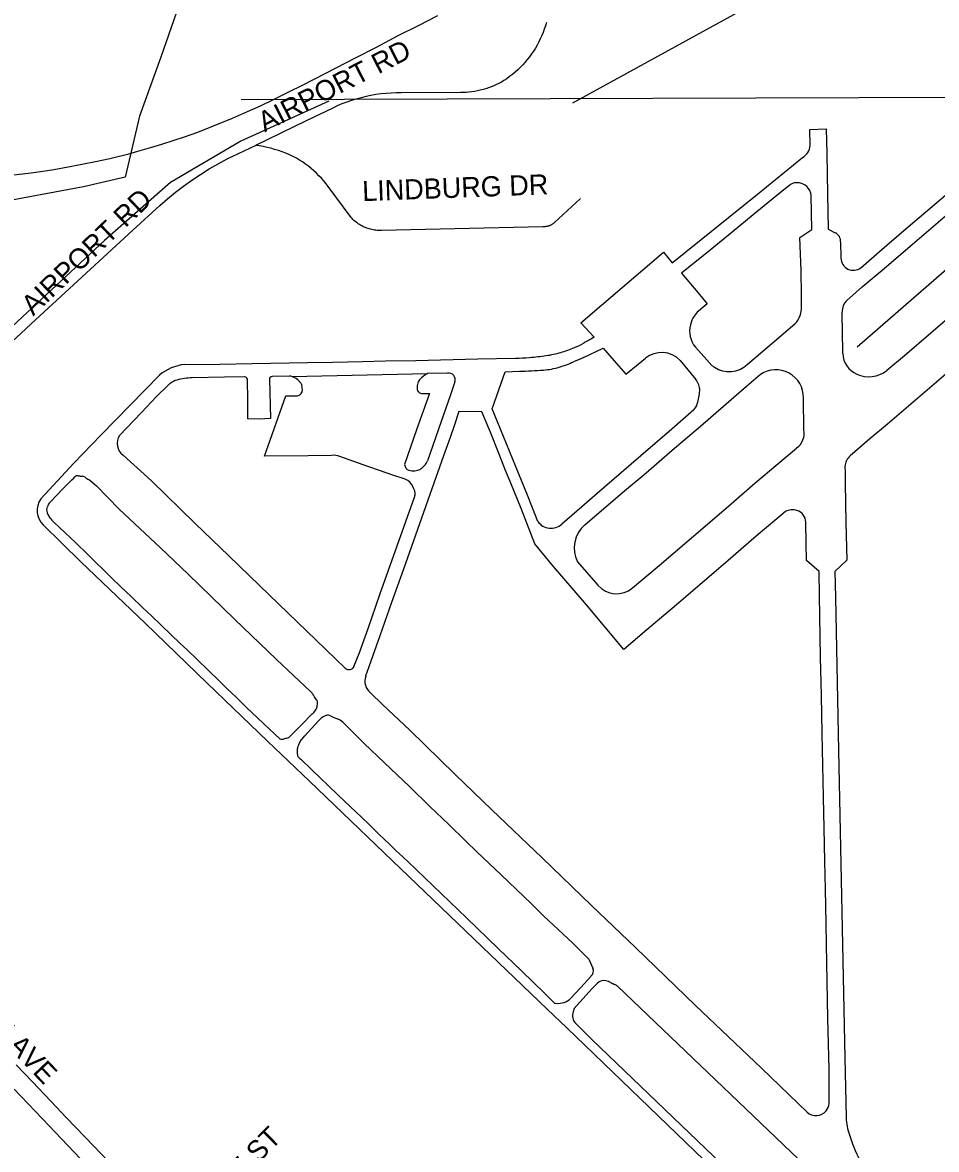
# Model space of a CAD drawing. Extents: x 1670563 to 1761545, y 515755 to 578944.
# Drawn here: x 1710407 to 1713800, y 545541 to 549724 of the extents above; entities that cross this region are included whole.
import ezdxf

# ---------------------------------------------------------------- set-up
doc = ezdxf.new("R2010")
doc.units = 0
for name, color, linetype in [('5_sectionlines', 7, 'Continuous'), ('AIRPORT', 7, 'Continuous'), ('RR Tracks', 7, 'Continuous'), ('SHP_LINE', 7, 'Continuous'), ('STREETCL', 7, 'Continuous'), ('STRNAMES', 7, 'Continuous')]:
    doc.layers.add(name, color=color, linetype=linetype)

# ---------------------------------------------------------------- blocks, each defined once
blk = doc.blocks.new('RR TRACKS02')
at = {"layer": 'RR Tracks'}
for p, q in [((1711947.7, 549748.9), (1711876.3, 549712.5)), ((1711876.3, 549712.5), (1711800.9, 549674.7)), ((1711800.9, 549674.7), (1711720, 549632.1)), ((1711720, 549632.1), (1711641.8, 549592)), ((1711641.8, 549592), (1711570.6, 549555.3)), ((1711570.6, 549555.3), (1711491.1, 549514)), ((1711440.4, 549488.5), (1711400, 549468.4)), ((1711491.1, 549514), (1711440.4, 549488.5)), ((1711337.9, 549437.6), (1711288.8, 549414.2)), ((1711400, 549468.4), (1711337.9, 549437.6)), ((1711288.8, 549414.2), (1711241.5, 549392.8)), ((1711185.1, 549367.8), (1711115.1, 549339.7)), ((1711241.5, 549392.8), (1711185.1, 549367.8)), ((1711056.3, 549316.3), (1711006.8, 549299.3)), ((1711115.1, 549339.7), (1711056.3, 549316.3)), ((1710922.7, 549271.8), (1710886.1, 549260.1)), ((1710969.3, 549286.4), (1710922.7, 549271.8)), ((1711006.8, 549299.3), (1710969.3, 549286.4)), ((1710797.1, 549235.2), (1710731.2, 549219.1)), ((1710833.6, 549245.2), (1710797.1, 549235.2)), ((1710886.1, 549260.1), (1710833.6, 549245.2)), ((1710576.2, 549187.2), (1710523, 549178.3)), ((1710678, 549207.4), (1710576.2, 549187.2)), ((1710731.2, 549219.1), (1710678, 549207.4)), ((1710407.4, 549162.2), (1710363.3, 549157.2)), ((1710438.8, 549165.7), (1710407.4, 549162.2)), ((1710499.3, 549173.9), (1710438.8, 549165.7)), ((1710523, 549178.3), (1710499.3, 549173.9)), ((1710384.2, 545855.4), (1710443.9, 545792.5)), ((1710443.9, 545792.5), (1710512.1, 545721)), ((1710512.1, 545721), (1710570.5, 545659.5)), ((1710570.5, 545659.5), (1710672.4, 545554)), ((1710672.4, 545554), (1710723.3, 545499.8))]:
    blk.add_line(p, q, dxfattribs=at)

msp = doc.modelspace()

# ---------------------------------------------------------------- linework, layer by layer
at = {"layer": '5_sectionlines'}
msp.add_line((1711218.5, 549438.3), (1714928.9, 549450.5), dxfattribs=at)
at = {"layer": 'AIRPORT'}
for points in [[(1713518.6, 548814), (1713588.3, 548874.7), (1713678.7, 548952.4), (1713817, 549070.1), (1713965, 549196), (1714098.4, 549308.4), (1714214.1, 549408.5), (1714289.7, 549474.3), (1714442.7, 549605.3), (1714538.1, 549688), (1714676.6, 549805.6), (1714813.3, 549922.6), (1714999.3, 550082), (1715171.6, 550229.9), (1715311.3, 550349.1), (1715419.2, 550442.5), (1715536.6, 550543), (1715643.7, 550634.5), (1715877.5, 550835.4), (1715970.6, 550913.6), (1716027.7, 550962.1), (1716141.7, 551060.4), (1716262, 551162.7)], [(1715379.7, 549742.6), (1715276.1, 549654.1), (1715180.7, 549572.3), (1715079.1, 549485.6), (1714992.5, 549412.2), (1714945.8, 549371.5), (1714858.7, 549296.9), (1714764, 549215.3), (1714651.7, 549119.5), (1714580.5, 549058.3), (1714498.4, 548988.4), (1714403.7, 548907.2), (1714321, 548836.5), (1714242.8, 548769.1), (1714177.9, 548713.7), (1714074.7, 548624.8), (1713983.7, 548547.3), (1713915.4, 548488.6), (1713825.5, 548411.7), (1713705, 548308.4), (1713617.6, 548234), (1713552.5, 548179.1), (1713479.7, 548116.1)], [(1713467.3, 548693), (1713524.6, 548743.2), (1713605.2, 548811.4), (1713711.3, 548901.3), (1713806.2, 548983.5), (1713915, 549076.9), (1714014, 549161.9), (1714113.8, 549247.2), (1714197.9, 549318.9), (1714378.3, 549472.6)], [(1713331.1, 549268.4), (1713329.7, 549327.9), (1713390.1, 549329.6), (1713392.7, 549238.3), (1713395.3, 549087.7), (1713397.3, 548957.7), (1713424.5, 548944.3)], [(1714575.4, 549255.1), (1714472.4, 549165.4), (1714364.8, 549072.9), (1713974.3, 548739.8), (1713680.9, 548487.7), (1713615.2, 548433.4)], [(1712529, 548556), (1712480.2, 548609.7), (1712786.6, 548872.7), (1712819.2, 548833.1), (1713135.4, 549087.8), (1713302.5, 549223.3)], [(1713255.9, 549120.9), (1713220.6, 549093), (1713120, 549010.6), (1713041.9, 548946.4), (1712960, 548880.1), (1712853.5, 548794.4), (1712913.9, 548723), (1712949, 548680.9), (1712916, 548653.7)], [(1713337.3, 548956.4), (1713334.6, 549082)], [(1713298.4, 548712.1), (1713297.9, 548803.6), (1713293.2, 548926.7), (1713337.3, 548956.4)], [(1713443.9, 548910.3), (1713445.4, 548849.5)], [(1713298.4, 548671.1), (1713298.4, 548712.1)], [(1713452.1, 548495.7), (1713450.8, 548580.9), (1713449.9, 548636.8), (1713449.6, 548649.8)], [(1713097.7, 548455.3), (1713213.4, 548554), (1713275.6, 548607.2)], [(1712489.3, 548480.7), (1712562.9, 548515.3), (1712603.6, 548468.7), (1712647.1, 548418.7), (1712692.9, 548456.6)], [(1712904.9, 548519.3), (1712947.2, 548472), (1712966.4, 548451.7)], [(1711008.9, 548455), (1711139.4, 548456.8), (1711260.2, 548458.3), (1711464.6, 548463.1), (1711558.3, 548464.2), (1711668.8, 548466.8), (1711754.3, 548468.6), (1711866.9, 548469.9), (1712097.9, 548476), (1712237.6, 548478.7)], [(1712692.9, 548456.6), (1712719.4, 548478.1)], [(1712848.7, 548470.1), (1712907.2, 548399.4)], [(1710697.8, 548192.8), (1710915.7, 548415.7)], [(1711231.8, 548409.2), (1711157.3, 548407.7), (1711037, 548405.6)], [(1711323.6, 548400.8), (1711327.2, 548254.3), (1711285.6, 548252.7), (1711243.9, 548253.8), (1711243.1, 548326.2), (1711242.8, 548396.3)], [(1711398.1, 548412.2), (1711334, 548410.7)], [(1711407.2, 548410.5), (1711911.1, 548422)], [(1712012.4, 548391), (1711994.8, 548339.1), (1711961.4, 548244), (1711910.8, 548097)], [(1711985.2, 548423), (1711911.1, 548422)], [(1712319.7, 547872.7), (1712283.9, 547964), (1712237.2, 548078.6), (1712170.9, 548241.8), (1712151.1, 548291), (1712199, 548427.6), (1712252.6, 548429.8)], [(1713146.2, 548417.7), (1713094.9, 548373.8), (1713018.9, 548308), (1712924.3, 548225.6), (1712819.3, 548136.5), (1712721.8, 548052.4), (1712634.6, 547979.3), (1712494.5, 547859.4)], [(1710946.1, 548377.5), (1710904.2, 548335.8), (1710849.4, 548277.1), (1710767.4, 548191.7)], [(1711554.4, 548117.9), (1711467.3, 548116.4), (1711304.9, 548114.6), (1711384.3, 548338.9), (1711427.9, 548338.9)], [(1711891.4, 548347.5), (1711917.7, 548347.5), (1711871, 548216.9), (1711825.7, 548083.4)], [(1713307.7, 548212.7), (1713306, 548330.5)], [(1712217.4, 548020.5), (1712200.5, 548061.5), (1712176.5, 548122.6), (1712142.6, 548206.9), (1712112.7, 548279.7), (1712026.7, 548280.4), (1712009.1, 548227.9), (1711994.1, 548183.7), (1711970, 548115.7)], [(1712899.3, 548286.4), (1712817.1, 548215), (1712702.3, 548115.8), (1712567.5, 548000.1), (1712409.4, 547862.2)], [(1710597.5, 548088.6), (1710697.8, 548192.8)], [(1712672.1, 547626.2), (1712770.8, 547708.7), (1712882.3, 547804.8), (1713028.3, 547929.9), (1713126.1, 548014.4), (1713210.5, 548086.6), (1713280.9, 548145.2)], [(1710780.3, 548118.6), (1710885.5, 548022.8), (1711048.2, 547865.3), (1711173.5, 547744.5), (1711286.3, 547634.6), (1711393.3, 547532.6), (1711497.8, 547432.5), (1711605.2, 547328.3)], [(1711827.7, 548029.6), (1711782.3, 548044.4), (1711672.1, 548083.3), (1711585.4, 548113.8)], [(1711970, 548115.7), (1711926.6, 547993.5), (1711888.6, 547885.1), (1711821.7, 547695.9), (1711776.7, 547571.6), (1711733.2, 547448.3), (1711693.1, 547333), (1711680.9, 547298.8)], [(1710475.1, 547956), (1710597.5, 548088.6)], [(1713460, 548076.5), (1713460.7, 548056.3), (1713461.4, 548014.2), (1713464, 547868.5), (1713467.3, 547728.8), (1713423, 547686.9), (1713425.5, 547590.4), (1713435.9, 547022.3), (1713459.6, 545881), (1713464.6, 545659.8)], [(1710509.7, 547944.4), (1710535.4, 547971.8), (1710555.4, 547992), (1710590.3, 548026.7), (1710596.3, 548032.5), (1710602, 548038.1)], [(1710656.9, 548026.2), (1710681.7, 548004.9), (1710766.2, 547918.6), (1710918.9, 547775), (1711021.8, 547676.3), (1711194.2, 547509.8), (1711350.6, 547359.6), (1711476.6, 547241.5)], [(1713239, 547909.6), (1713207.8, 547882.8), (1713131.2, 547817.5), (1713026.4, 547727.4), (1712992.2, 547697.8), (1712921, 547637.2), (1712834.5, 547563.2), (1712725.3, 547470.1), (1712639.4, 547397.6), (1712501.2, 547563.4), (1712371, 547714.3), (1712308.9, 547789.8), (1712258.4, 547920.6), (1712217.4, 548020.5)], [(1711637.7, 547333.8), (1711656.3, 547382.7), (1711690.1, 547475.5), (1711733.9, 547601.5), (1711862.9, 547963.3)], [(1710623.2, 547722.9), (1710484, 547859.8)], [(1711361.9, 547065.7), (1711342.3, 547084), (1711302.2, 547122.5), (1711237.8, 547183.3), (1711200.2, 547220), (1711166, 547252.3), (1711136.8, 547281.1), (1711097.7, 547318.8), (1711053.8, 547361.6), (1711018.2, 547395.5), (1710991.2, 547421.1), (1710959.1, 547452), (1710922.2, 547488.1), (1710886.2, 547522.2), (1710854.2, 547552.5), (1710810.6, 547594.5), (1710771.5, 547631.6), (1710737.4, 547663.5), (1710647.8, 547750.8), (1710604.8, 547793.5), (1710544.9, 547850.6), (1710523.6, 547870.3)], [(1713402.1, 545722.3), (1713401.5, 545837.7), (1713396.6, 546029.1), (1713391.8, 546302.4), (1713390.4, 546380.4), (1713387.7, 546507.5), (1713385.5, 546612.1), (1713383.1, 546734.7), (1713380.7, 546848.8), (1713375.4, 547087.1), (1713372.6, 547226.2), (1713369.6, 547368.9), (1713365.3, 547597.5), (1713363.9, 547686.9), (1713317.6, 547728.2), (1713316.8, 547792.3), (1713315, 547870)], [(1710863.4, 547493.5), (1710623.2, 547722.9)], [(1712467.4, 547723.1), (1712542.6, 547635.9)], [(1711092.8, 547272.7), (1710863.4, 547493.5)], [(1711316.8, 547057.4), (1711092.8, 547272.7)], [(1711699, 547236.3), (1711743.1, 547192.8), (1711844.8, 547098.4), (1712013.5, 546932.7), (1712149.8, 546802.4), (1712336.4, 546624.3), (1712519.9, 546447.1), (1712682.6, 546290.9), (1712905.8, 546076.2), (1713149.9, 545843.2), (1713319.7, 545680.3)], [(1711482.7, 547158.2), (1711443.7, 547118.5), (1711398.1, 547072.6), (1711394.3, 547069.1)], [(1711442.3, 547062.4), (1711455.6, 547076.9), (1711479.8, 547103.9), (1711506.4, 547132.5), (1711514.8, 547140.9)], [(1711550.1, 547151.4), (1711560.4, 547146.7), (1711576.5, 547139.7)], [(1711595.7, 547127.6), (1711617, 547106.9), (1711675.7, 547048.9), (1711750.7, 546977.2), (1711843.6, 546888.3), (1711919.8, 546814.3), (1711989.9, 546747.7), (1712053, 546685.8), (1712093.4, 546646.3), (1712183.9, 546560.7), (1712296.6, 546453.2), (1712343, 546408), (1712450.5, 546307.2), (1712510, 546247.7)], [(1711472.8, 546909), (1711316.8, 547057.4)], [(1712379.3, 546087.3), (1712366.8, 546099.7), (1712344.6, 546121.7), (1712260.9, 546203.1), (1712172.8, 546287.6), (1712055.8, 546401), (1711839.1, 546609), (1711820.4, 546625.9), (1711807.1, 546639), (1711793.4, 546651.8), (1711768.9, 546674.8), (1711729.7, 546712.4), (1711691.3, 546750.3), (1711666.2, 546773.5), (1711624, 546814.6), (1711579.5, 546857), (1711541.9, 546892.8), (1711513.3, 546920.2), (1711481.6, 546951), (1711439.9, 546989.7)], [(1711750, 546642.3), (1711472.8, 546909)], [(1712354.9, 546061.7), (1711750, 546642.3)], [(1712510, 546247.7), (1712524.4, 546214.2)], [(1712517.3, 546184.1), (1712479.6, 546142.3), (1712441.2, 546101.5)], [(1712541.3, 546158.6), (1712521.2, 546137.4), (1712455.6, 546064.8), (1712451.4, 546052.6)], [(1713484.7, 545316.9), (1712615.7, 546147.6)], [(1712427.2, 545992.9), (1712354.9, 546061.7)], [(1712461.1, 546008.5), (1712520.8, 545949.4), (1713303.5, 545198.5), (1713354, 545151.7)], [(1713175.6, 545272.9), (1712427.2, 545992.9)], [(1713401.8, 545711.7), (1713402.1, 545722.3)], [(1713477.5, 545595.5), (1713488.8, 545562)]]:
    msp.add_lwpolyline(points, dxfattribs=at)
for centre, radius, start, end in [((1713273.6, 549273.3), 57.7, 300.0178, 355.1523), ((1713277.1, 549097.8), 31.4, 111.7027, 132.5024), ((1713282, 549085.6), 44.5, 78.318, 111.7027), ((1713278.4, 549068.3), 62.1, 50.1029, 78.318), ((1713289, 549081), 45.6, 1.2206, 50.1029), ((1713409.1, 548912.9), 34.9, 355.7562, 63.7629), ((1713491.2, 548850.7), 45.8, 181.4075, 306.7105), ((1713507.8, 548651.2), 58.2, 134.0763, 181.369), ((1713073.1, 548512.9), 210.9, 138.1428, 144.8238), ((1713210.7, 548666.4), 87.8, 317.6608, 3.1192), ((1712980.4, 548580), 96.8, 166.3678, 218.802), ((1712976.6, 548580.9), 92.9, 144.8238, 166.3678), ((1712336.2, 548765), 273.8, 284.6323, 295.869), ((1712396.5, 548695.6), 186.6, 288.4827, 300.7304), ((1712920.3, 547814.5), 838.5, 117.8236, 120.7304), ((1712221.7, 549282.1), 803.5, 271.1327, 274.8213), ((1712170.9, 549884.2), 1407.8, 274.8213, 277.365), ((1712293.4, 548876.5), 392.7, 278.4932, 286.5706), ((1713029.7, 547155.5), 1431.1, 112.1874, 113.8039), ((1712779.7, 548403.8), 95.7, 43.8429, 129.0195), ((1713541.7, 548500.5), 89.8, 183.0368, 245.0352), ((1711024.3, 548288.5), 167.2, 95.2742, 130.4699), ((1712129.8, 551440), 3012.7, 272.3367, 274.0214), ((1712322.4, 548700.9), 266.9, 274.0214, 286.8144), ((1712266.6, 548885.4), 459.6, 286.8144, 293.8039), ((1712988.1, 548472.3), 29.9, 223.4228, 245.701), ((1713030.3, 548527.4), 98.8, 236.5412, 313.0437), ((1713203.9, 548333.4), 102.2, 358.38, 124.3593), ((1713548.2, 548514.4), 105.1, 245.0352, 309.5557), ((1710999.4, 548328.4), 71.5, 105.7964, 126.4557), ((1711040.9, 548181.8), 223.9, 90.9987, 105.7964), ((1711229.7, 548396.3), 13.2, 0.1848, 80.5881), ((1711334.2, 548400), 10.7, 91.2613, 175.8478), ((1711396.3, 548377.1), 35.1, 71.9811, 87.0144), ((1711386, 548347.4), 66.5, 40.9863, 71.4252), ((1711401.1, 548356.6), 49.2, 30.6522, 44.4825), ((1711904.9, 548377.1), 32, 137.844, 172.0747), ((1711964.4, 548323.2), 112.3, 118.3283, 137.844), ((1711988.9, 548398.6), 24.7, 342.008, 98.6414), ((1712860.2, 548360.6), 60.9, 357.6745, 39.5931), ((1711115.4, 548171.4), 266.8, 126.4557, 129.3978), ((1711424.9, 548360), 21.3, 278.0211, 6.501), ((1711364.5, 548361.2), 81.6, 0.8347, 14.5494), ((1711991.4, 548365.1), 119.3, 172.0747, 179.7405), ((1711890.2, 548365.5), 18.1, 179.7405, 273.9076), ((1712743, 548365.3), 178.2, 341.6137, 357.6745), ((1712847.7, 548330.5), 67.9, 319.5002, 341.6137), ((1710812.1, 548161.9), 53.7, 146.2507, 233.6743), ((1713241.7, 548199.9), 67.3, 305.6683, 11.0004), ((1711560, 548041.5), 76.6, 70.6139, 94.1537), ((1711846.7, 548127.1), 70.9, 301.9709, 334.8724), ((1713517.2, 548072.8), 57.3, 130.8987, 176.2818), ((1711850.4, 548085.6), 24.8, 185.0726, 249.3128), ((1711857.7, 548113.2), 53.2, 252.3955, 299.7987), ((1710612.4, 548027.3), 15, 81.2401, 133.9502), ((1710677.2, 548447.8), 410.5, 261.2401, 263.2129), ((1710625.3, 548011.5), 28.9, 53.9538, 83.2129), ((1710695.5, 548108), 90.5, 233.9538, 244.7563), ((1711819.2, 548001.8), 29.1, 51.6496, 72.9928), ((1711791.2, 547966.5), 74.1, 21.6673, 51.6496), ((1711828.3, 547975.6), 36.7, 340.4621, 29.8738), ((1710535.5, 547913.1), 74.1, 144.638, 225.964), ((1710536.5, 547918.1), 37.5, 135.4848, 166.1189), ((1710509.4, 547913.6), 12.7, 162.1648, 190.6348), ((1710551.9, 547921.6), 55.9, 190.6348, 219.7766), ((1710360.2, 547961.6), 144.1, 342.1648, 346.1189), ((1713265.3, 547858.6), 57.4, 72.9211, 117.2151), ((1713268.4, 547868.9), 46.6, 1.3634, 72.9211), ((1710635.4, 547991.1), 164.6, 219.7766, 227.2201), ((1712369.3, 547908.1), 60.9, 215.5521, 311.0982), ((1712567.7, 547774), 112.5, 130.5771, 206.8978), ((1712612.2, 547696), 92, 220.8048, 310.5927), ((1711619.5, 547343), 20.5, 225.8591, 333.392), ((1711733.4, 547280.1), 55.6, 160.3736, 231.9161), ((1711441.3, 547203.8), 51.6, 33.9692, 46.8721), ((1710620.5, 546650.8), 1041.3, 33.2264, 33.9692), ((1710604.6, 546640.4), 1060.4, 32.3241, 33.2264), ((1711476.2, 547188.5), 24.6, 318.5692, 2.7357), ((1711472.1, 547198.3), 30, 343.2597, 17.7036), ((1711454.8, 547194.2), 45.5, 307.7345, 331.0592), ((1711546.5, 547109), 44.9, 117.7952, 134.7711), ((1711545.7, 547110.4), 43.3, 103.0114, 117.7952), ((1711541.1, 547130.6), 22.6, 66.4862, 103.0114), ((1711545, 547068), 78.3, 49.6191, 66.3264), ((1711371, 547095.9), 31.5, 253.2359, 284.0005), ((1711568.4, 546304.3), 784.4, 102.8279, 104.0005), ((1711471.3, 547035.3), 39.6, 136.9605, 160.7639), ((1711455.3, 547021.6), 29.1, 162.2976, 189.9357), ((1711485.1, 547014.6), 58.5, 178.0276, 189.7327), ((1711477.1, 547023.2), 50, 149.7577, 171.6721), ((1711436.4, 547006.2), 9.13, 189.7327, 221.7568), ((1711544.9, 547103), 154.5, 221.7568, 227.1666), ((1712500.6, 546203.9), 25.9, 310.2202, 23.2801), ((1712565.6, 546133.7), 34.8, 77.3553, 134.2929), ((1712559, 546104.5), 64.7, 60.6496, 77.3553), ((1712650.6, 546267.3), 122, 240.6496, 248.6869), ((1712595.7, 546126.6), 29, 46.2897, 68.6869), ((1712403.7, 546136.8), 51.5, 286.4097, 316.7724), ((1712387.2, 546095.2), 11.1, 225.0994, 265.3755), ((1712393.4, 546171.9), 88.1, 265.3755, 286.4097), ((1712491.8, 546038.5), 42.8, 160.6691, 224.3308), ((1713352.8, 545714.8), 47.8, 226.1852, 320.9293), ((1713346.9, 545719.6), 55.5, 320.9293, 351.7741), ((1713652.8, 545664), 188.3, 181.2869, 201.3518), ((1713825.7, 545676), 355.7, 198.6889, 215.2831)]:
    msp.add_arc(centre, radius, start, end, dxfattribs=at)
at = {"layer": 'SHP_LINE'}
for points in [[(1717757, 552089), (1717657, 552110), (1717588, 552063), (1717456, 551957), (1713505, 548519)], [(1715432, 551217), (1715124, 550964), (1714913, 550800), (1714639, 550652), (1713529, 550019), (1712449, 549425)], [(1711171, 550877), (1711046, 550705), (1711022, 550432), (1711038, 550143), (1711007, 549846), (1710921, 549596), (1710842, 549377), (1710788, 549150), (1710633, 549115), (1710300, 549053), (1710075, 549042), (1709887, 549046), (1709122, 549050), (1708320, 549064), (1708243, 549039), (1708228, 548975), (1708213, 548777)], [(1711544, 549432), (1711218, 549284), (1710956, 549131), (1710712, 548915), (1710082, 548330), (1709536, 547810), (1709039, 547353), (1709012, 547349), (1708985, 547360), (1708962, 547387), (1708534, 547859), (1708290, 548099)]]:
    msp.add_lwpolyline(points, dxfattribs=at)
at = {"layer": 'STREETCL'}
for points in [[(1712351.7, 549725.2), (1712348, 549712.7), (1712344, 549700.3), (1712339.5, 549688.1), (1712334.6, 549676), (1712329.3, 549664.1), (1712323.5, 549652.4), (1712317.4, 549640.9), (1712310.9, 549629.6), (1712303.9, 549618.6), (1712296.6, 549607.8), (1712289, 549597.3), (1712281, 549587), (1712272.6, 549577), (1712263.9, 549567.4), (1712254.8, 549558), (1712245.4, 549548.9), (1712235.8, 549540.2), (1712225.8, 549531.8), (1712215.5, 549523.8), (1712205, 549516.1), (1712194.2, 549508.8), (1712185.1, 549503.5), (1712175.7, 549498.5), (1712166.2, 549493.9), (1712156.6, 549489.5), (1712146.8, 549485.5), (1712136.8, 549481.9), (1712126.8, 549478.6), (1712116.6, 549475.6), (1712106.4, 549473), (1712096, 549470.7), (1712085.6, 549468.8), (1712075.2, 549467.2), (1712064.6, 549466), (1712054.1, 549465.2), (1712043.5, 549464.8), (1712032.9, 549464.7), (1711812.6, 549463.4), (1711793.9, 549463.3), (1711775.2, 549462.6), (1711756.5, 549461.3), (1711737.8, 549459.4), (1711719.3, 549456.8), (1711700.8, 549453.7), (1711682.5, 549449.9), (1711664.2, 549445.5), (1711646.2, 549440.6), (1711628.3, 549435), (1711610.6, 549428.9), (1711593.1, 549422.2), (1711575.8, 549414.9), (1711558.8, 549407.1), (1711459.7, 549359.3), (1711271.5, 549268.6)], [(1709534.6, 547772.1), (1709694, 547918.8), (1710119.8, 548309.9), (1710455.9, 548621), (1710817.3, 548953.6), (1710916.9, 549044.8), (1710945.4, 549070.1), (1710974.8, 549094.4), (1711005, 549117.6), (1711035.9, 549139.9), (1711067.6, 549161), (1711099.9, 549181.1), (1711133, 549200.1), (1711166.6, 549218), (1711271.5, 549268.6)], [(1712479, 549071.9), (1712382.6, 548982.4), (1712381, 548981), (1712379.4, 548979.7), (1712377.8, 548978.4), (1712376.1, 548977.2), (1712374.4, 548976), (1712372.6, 548974.9), (1712370.8, 548973.9), (1712369, 548972.9), (1712367.1, 548972), (1712365.2, 548971.1), (1712363.3, 548970.3), (1712361.4, 548969.6), (1712359.4, 548969), (1712357.4, 548968.4), (1712355.4, 548967.9), (1712353.4, 548967.4), (1712351.3, 548967.1), (1712349.3, 548966.8), (1712347.2, 548966.5), (1712345.1, 548966.4), (1712343.1, 548966.3), (1712341, 548966.2), (1712338.9, 548966.3), (1711739.4, 548952.5), (1711734.3, 548952.5), (1711729.3, 548952.6), (1711724.2, 548953), (1711719.2, 548953.4), (1711714.2, 548954.1), (1711709.2, 548954.9), (1711704.3, 548955.9), (1711699.4, 548957.1), (1711694.5, 548958.4), (1711689.7, 548959.9), (1711684.9, 548961.6), (1711680.2, 548963.4), (1711675.6, 548965.4), (1711671, 548967.6), (1711666.5, 548969.9), (1711662.1, 548972.3), (1711657.7, 548974.9), (1711653.5, 548977.7), (1711649.4, 548980.6), (1711645.3, 548983.6), (1711641.4, 548986.8), (1711637.6, 548990.1), (1711633.9, 548993.5), (1711630.3, 548997.1), (1711626.8, 549000.7), (1711541.8, 549115.5), (1711533.8, 549126), (1711525.4, 549136.3), (1711516.7, 549146.2), (1711507.6, 549155.8), (1711498.2, 549165.2), (1711488.6, 549174.2), (1711478.6, 549182.9), (1711468.3, 549191.3), (1711457.8, 549199.3), (1711447, 549206.9), (1711436, 549214.2), (1711424.7, 549221.1), (1711411.6, 549227.7), (1711398.2, 549233.7), (1711384.7, 549239.4), (1711371, 549244.6), (1711357.2, 549249.4), (1711343.2, 549253.7), (1711329, 549257.6), (1711314.8, 549261.1), (1711300.5, 549264), (1711286, 549266.5), (1711271.5, 549268.6)], [(1710644.5, 545483.7), (1710505.8, 545629.5), (1710376, 545765.4)]]:
    msp.add_lwpolyline(points, dxfattribs=at)

# ---------------------------------------------------------------- block references
msp.add_blockref('RR TRACKS02', (0, 0), dxfattribs=at)

# ---------------------------------------------------------------- texts
at = {"layer": 'STRNAMES'}
for s, rotation, p in [('AIRPORT RD', 27.1055, (1711305.9, 549316.3)), ('LINDBURG DR', 2.1269, (1711669.6, 549061.3)), ('AIRPORT RD', 43.7399, (1710446.7, 548633.3)), ('NETTLETON AVE', 313.5044, (1709919.8, 546376.6)), ('DUKE ST', 44.7988, (1711064.9, 545273.2))]:
    msp.add_text(s, height=75, rotation=rotation, dxfattribs=at).set_placement(p)

doc.saveas('drawing.dxf')
